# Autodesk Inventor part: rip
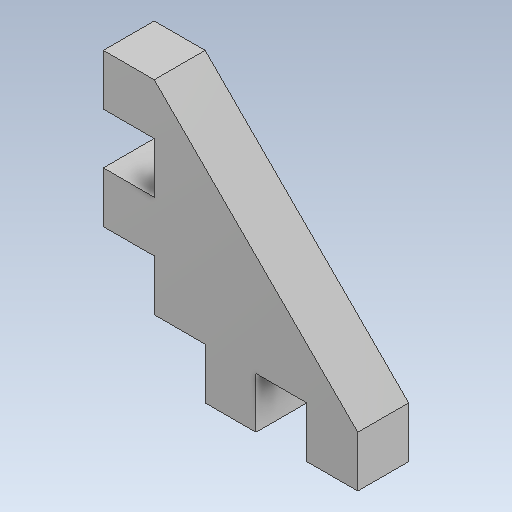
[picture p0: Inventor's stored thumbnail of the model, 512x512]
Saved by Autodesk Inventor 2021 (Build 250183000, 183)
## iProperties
Created: 2026-10
Part Number: rip
Material: Generic
Document SubType Name: Modeling
Designer: hp
Density: 1 g/cm^3
Appearance: Default
Author: hp
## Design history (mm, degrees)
feature "Body1"
body "Solid1"
